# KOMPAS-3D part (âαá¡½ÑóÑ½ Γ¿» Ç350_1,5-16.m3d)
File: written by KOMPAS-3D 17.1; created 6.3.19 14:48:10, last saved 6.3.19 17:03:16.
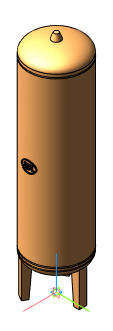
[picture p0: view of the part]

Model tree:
1. Операция без истории:1  (with: Сечение модели:1)

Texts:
  Гранлевел тип А100_1,5-16
  Гранлевел тип А150_1,5-16
  Гранлевел тип А220_1,5-16
  Гранлевел тип А350_1,5-16
  Гранлевел тип А500_1,5-16
  Гранлевел тип А700_1,5-16
  Гранлевел тип А900_1,5-16
  Гранлевел тип А1000_1,5-16
  Гранлевел тип А1400_1,5-16
  Точка начала. Х
  Точка начала. Y
  Точка начала. Z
